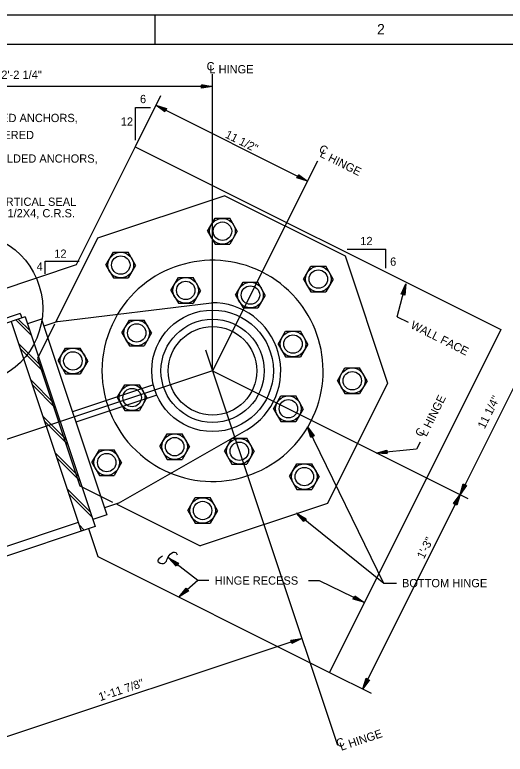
# Model space of a CAD drawing. Extents: x 0.1 to 13.5, y 0.1 to 9.5.
# Drawn here: x 7.414 to 10.186, y 5.277 to 9.458 of the extents above; entities that cross this region are included whole.
import ezdxf

# ---------------------------------------------------------------- set-up
doc = ezdxf.new("R2010")
doc.units = 0
for name, color, linetype in [('Level 1', 7, 'Continuous'), ('Level 13', 7, 'Continuous'), ('Level 25', 7, 'Continuous'), ('Level 3', 7, 'Continuous'), ('Level 44', 7, 'Continuous'), ('Level 50', 7, 'Continuous')]:
    doc.layers.add(name, color=color, linetype=linetype)

msp = doc.modelspace()

# ---------------------------------------------------------------- linework, layer by layer
at = {"layer": 'Level 1'}
for p, q in [((8.2083, 9.2917), (8.2083, 9.4583)), ((8.532, 7.445), (8.532, 9.1229)), ((8.0959, 8.7486), (8.0959, 8.9346)), ((8.0959, 8.9346), (8.1812, 8.9346)), ((8.2113, 8.9466), (9.0685, 8.518)), ((9.2936, 8.1324), (9.5107, 8.1324)), ((9.5107, 8.0265), (9.5107, 8.1324)), ((7.5853, 7.9944), (7.5853, 8.0646)), ((7.5853, 8.0646), (7.7779, 8.0646)), ((9.5758, 7.7512), (9.625, 7.9362)), ((9.5758, 7.7512), (9.6384, 7.7199)), ((10.3502, 7.5841), (9.9309, 6.7456)), ((8.4925, 7.5636), (9.2376, 5.3283)), ((8.532, 7.445), (9.9751, 6.7235)), ((9.7047, 7.0415), (9.6849, 7.0021)), ((9.9309, 6.7456), (9.3812, 5.6462)), ((9.1935, 5.74), (9.429, 5.6223))]:
    msp.add_line(p, q, dxfattribs=at)
for points in [[(0.125, 9.4583), (13.4583, 9.4583), (13.4583, 0.125), (0.125, 0.125)], [(0.625, 9.2917), (13.2917, 9.2917), (13.2917, 0.2917), (0.625, 0.2917)]]:
    msp.add_lwpolyline(points, close=True, dxfattribs=at)
msp.add_spline([(8.2493, 6.3964), (8.2228, 6.3676), (8.2541, 6.3555), (8.2926, 6.4085), (8.3239, 6.4181), (8.3311, 6.4037)], degree=3, dxfattribs=at)
at = {"layer": 'Level 13'}
for p, q in [((8.5043, 8.2349), (8.5463, 8.3076)), ((8.5463, 8.3076), (8.6299, 8.3076)), ((8.6719, 8.2349), (8.6299, 8.3076)), ((8.5043, 8.2349), (8.5463, 8.1622)), ((8.6719, 8.2349), (8.6299, 8.1622)), ((8.5463, 8.1622), (8.6299, 8.1622)), ((7.9295, 8.0433), (7.9715, 8.116)), ((7.9715, 8.116), (8.0551, 8.116)), ((8.0971, 8.0433), (8.0551, 8.116)), ((7.9295, 8.0433), (7.9715, 7.9705)), ((8.0971, 8.0433), (8.0551, 7.9705)), ((9.0463, 7.9639), (9.0883, 8.0366)), ((9.0883, 8.0366), (9.1719, 8.0366)), ((9.2139, 7.9639), (9.1719, 8.0366)), ((7.9715, 7.9705), (8.0551, 7.9705)), ((8.2967, 7.8998), (8.3387, 7.9725)), ((8.3387, 7.9725), (8.4223, 7.9725)), ((8.4643, 7.8998), (8.4223, 7.9725)), ((8.6625, 7.8738), (8.7045, 7.9465)), ((8.7045, 7.9465), (8.7881, 7.9465)), ((8.8301, 7.8738), (8.7881, 7.9465)), ((9.0463, 7.9639), (9.0883, 7.8912)), ((9.2139, 7.9639), (9.1719, 7.8912)), ((8.2967, 7.8998), (8.3387, 7.8271)), ((8.4643, 7.8998), (8.4223, 7.8271)), ((8.6625, 7.8738), (8.7045, 7.8011)), ((8.8301, 7.8738), (8.7881, 7.8011)), ((9.0883, 7.8912), (9.1719, 7.8912)), ((8.3387, 7.8271), (8.4223, 7.8271)), ((8.7045, 7.8011), (8.7881, 7.8011)), ((8.0196, 7.6595), (8.0616, 7.7322)), ((8.0616, 7.7322), (8.1452, 7.7322)), ((8.1872, 7.6595), (8.1452, 7.7322)), ((8.0196, 7.6595), (8.0616, 7.5868)), ((8.1872, 7.6595), (8.1452, 7.5868)), ((8.9028, 7.5967), (8.9448, 7.6695)), ((8.9448, 7.6695), (9.0284, 7.6695)), ((9.0704, 7.5967), (9.0284, 7.6695)), ((7.6585, 7.5013), (7.7005, 7.574)), ((7.7005, 7.574), (7.7841, 7.574)), ((7.8261, 7.5013), (7.7841, 7.574)), ((8.0616, 7.5868), (8.1452, 7.5868)), ((8.9028, 7.5967), (8.9448, 7.524)), ((9.0704, 7.5967), (9.0284, 7.524)), ((7.6585, 7.5013), (7.7005, 7.4286)), ((7.8261, 7.5013), (7.7841, 7.4286)), ((8.9448, 7.524), (9.0284, 7.524)), ((9.2379, 7.3891), (9.2799, 7.4618)), ((9.2799, 7.4618), (9.3635, 7.4618)), ((9.4055, 7.3891), (9.3635, 7.4618)), ((7.7005, 7.4286), (7.7841, 7.4286)), ((7.9936, 7.2937), (8.0356, 7.3664)), ((8.0356, 7.3664), (8.1192, 7.3664)), ((8.1612, 7.2937), (8.1192, 7.3664)), ((9.2379, 7.3891), (9.2799, 7.3164)), ((9.4055, 7.3891), (9.3635, 7.3164)), ((7.9936, 7.2937), (8.0356, 7.221)), ((8.1612, 7.2937), (8.1192, 7.221)), ((8.8768, 7.2309), (8.9188, 7.3036)), ((8.9188, 7.3036), (9.0024, 7.3036)), ((9.0444, 7.2309), (9.0024, 7.3036)), ((9.2799, 7.3164), (9.3635, 7.3164)), ((8.0356, 7.221), (8.1192, 7.221)), ((8.8768, 7.2309), (8.9188, 7.1582)), ((9.0444, 7.2309), (9.0024, 7.1582)), ((8.9188, 7.1582), (9.0024, 7.1582)), ((8.2339, 7.0166), (8.2759, 7.0894)), ((8.2759, 7.0894), (8.3595, 7.0894)), ((8.4015, 7.0166), (8.3595, 7.0894)), ((8.5997, 6.9906), (8.6417, 7.0634)), ((8.6417, 7.0634), (8.7253, 7.0634)), ((8.7673, 6.9906), (8.7253, 7.0634)), ((7.8501, 6.9265), (7.8921, 6.9992)), ((7.8921, 6.9992), (7.9757, 6.9992)), ((8.0177, 6.9265), (7.9757, 6.9992)), ((8.2339, 7.0166), (8.2759, 6.9439)), ((8.4015, 7.0166), (8.3595, 6.9439)), ((8.5997, 6.9906), (8.6417, 6.9179)), ((8.7673, 6.9906), (8.7253, 6.9179)), ((8.2759, 6.9439), (8.3595, 6.9439)), ((7.8501, 6.9265), (7.8921, 6.8538)), ((8.0177, 6.9265), (7.9757, 6.8538)), ((8.6417, 6.9179), (8.7253, 6.9179)), ((8.9669, 6.8471), (9.0089, 6.9199)), ((9.0089, 6.9199), (9.0925, 6.9199)), ((9.1345, 6.8471), (9.0925, 6.9199)), ((7.8921, 6.8538), (7.9757, 6.8538)), ((8.9669, 6.8471), (9.0089, 6.7744)), ((9.1345, 6.8471), (9.0925, 6.7744)), ((9.0089, 6.7744), (9.0925, 6.7744)), ((8.3921, 6.6555), (8.4341, 6.7283)), ((8.4341, 6.7283), (8.5177, 6.7283)), ((8.5597, 6.6555), (8.5177, 6.7283)), ((8.3921, 6.6555), (8.4341, 6.5828)), ((8.5597, 6.6555), (8.5177, 6.5828)), ((8.4341, 6.5828), (8.5177, 6.5828))]:
    msp.add_line(p, q, dxfattribs=at)
for centre in [(8.5881, 8.2347), (8.0133, 8.0431), (9.1301, 7.9637), (8.3805, 7.8996), (8.7463, 7.8736), (8.1034, 7.6593), (8.9866, 7.5965), (7.7423, 7.5011), (9.3217, 7.3889), (8.0774, 7.2935), (8.9606, 7.2307), (8.3177, 7.0164), (8.6835, 6.9904), (7.9339, 6.9263), (9.0507, 6.8469), (8.4759, 6.6553)]:
    msp.add_circle(centre, 0.0725, dxfattribs=at)
at = {"layer": 'Level 25'}
for p, q in [((8.532, 9.053), (6.3151, 9.053)), ((8.2379, 8.9997), (8.0941, 8.7121)), ((8.0941, 8.7121), (7.7601, 8.0442)), ((8.0941, 8.7121), (10.1624, 7.6779)), ((9.1252, 8.6314), (8.532, 7.445)), ((8.6023, 8.4347), (7.8819, 8.1946)), ((8.6023, 8.4347), (9.2816, 8.0951)), ((7.8819, 8.1946), (7.6461, 7.723)), ((9.2816, 8.0951), (9.5217, 7.3747)), ((7.7601, 8.0442), (7.0398, 7.8041)), ((7.6573, 7.7244), (8.5256, 7.8304)), ((7.4448, 7.7689), (5.3399, 7.0673)), ((7.4728, 7.7508), (5.3482, 7.0426)), ((7.4448, 7.7689), (7.4531, 7.7442)), ((7.4728, 7.7508), (7.8681, 6.5649)), ((7.5651, 7.7376), (7.486, 7.7113)), ((7.5651, 7.7376), (7.934, 6.6308)), ((7.3938, 7.7244), (7.7891, 6.5386)), ((7.6388, 7.7084), (7.5423, 7.5154)), ((7.6573, 7.7244), (7.5782, 7.6981)), ((10.1624, 7.6779), (9.1935, 5.74)), ((7.5423, 7.5154), (7.7824, 6.795)), ((8.532, 7.445), (5.337, 6.38)), ((8.1974, 7.3664), (7.7396, 7.2138)), ((9.5217, 7.3747), (9.1821, 6.6955)), ((8.2171, 7.3071), (7.7594, 7.1546)), ((7.9999, 6.6967), (8.7255, 7.1117)), ((7.7824, 6.7949), (7.9671, 6.7026)), ((7.9999, 6.6967), (7.9208, 6.6703)), ((7.9901, 6.6911), (8.4617, 6.4553)), ((9.1821, 6.6955), (8.4617, 6.4553)), ((7.934, 6.6308), (7.8549, 6.6044)), ((7.7726, 6.588), (5.727, 5.9061)), ((7.8681, 6.5649), (5.7435, 5.8567)), ((7.831, 6.5526), (7.8835, 6.395)), ((7.8835, 6.395), (9.1935, 5.74)), ((9.0362, 5.9324), (7.1487, 5.3032))]:
    msp.add_line(p, q, dxfattribs=at)
for centre, radius in [((8.5881, 8.2347), 0.0521), ((7.1424, 7.7968), 0.4297), ((8.0133, 8.0431), 0.0521), ((9.1301, 7.9637), 0.0521), ((8.3805, 7.8996), 0.0521), ((8.7463, 7.8736), 0.0521), ((8.532, 7.445), 0.3438), ((8.532, 7.445), 0.2917), ((8.1034, 7.6593), 0.0521), ((8.532, 7.445), 0.25), ((8.9866, 7.5965), 0.0521), ((7.7423, 7.5011), 0.0521), ((9.3217, 7.3889), 0.0521), ((8.0774, 7.2935), 0.0521), ((8.9606, 7.2307), 0.0521), ((8.3177, 7.0164), 0.0521), ((8.6835, 6.9904), 0.0521), ((7.9339, 6.9263), 0.0521), ((9.0507, 6.8469), 0.0521), ((8.4759, 6.6553), 0.0521)]:
    msp.add_circle(centre, radius, dxfattribs=at)
for radius, start, end in [(0.625, 243.8888, 149.1319), (0.3854, 300.1282, 90.9539), (0.625, 149.1319, 247.8392), (0.625, 152.8609, 153.0479)]:
    msp.add_arc((8.532, 7.445), radius, start, end, dxfattribs=at)
at = {"layer": 'Level 3'}
for p, q in [((9.0692, 7.1281), (9.0692, 7.1281)), ((9.0768, 7.1125), (9.0768, 7.1125)), ((9.6849, 7.0021), (9.4563, 6.98)), ((9.4563, 6.98), (9.4563, 6.98)), ((9.4736, 6.9817), (9.4736, 6.9817)), ((9.4999, 6.2424), (9.0066, 6.6395)), ((9.0066, 6.6395), (9.0066, 6.6395)), ((9.0201, 6.6287), (9.0201, 6.6287)), ((8.449, 6.2593), (8.283, 6.3868)), ((8.283, 6.3868), (8.283, 6.3868)), ((8.2967, 6.3763), (8.2967, 6.3763)), ((8.3431, 6.1678), (8.3431, 6.1678)), ((8.3563, 6.1791), (8.3563, 6.1791)), ((9.3718, 6.1441), (9.3718, 6.1441)), ((9.3874, 6.1365), (9.3874, 6.1365))]:
    msp.add_line(p, q, dxfattribs=at)
for points in [[(9.5721, 6.2424), (9.4999, 6.2424), (9.0692, 7.1281)], [(9.0871, 7.0676), (9.0692, 7.1281), (9.1057, 7.0766), (9.0898, 7.0689), (9.0768, 7.1125), (9.1016, 7.0775), (9.0914, 7.0726), (9.084, 7.0976), (9.0974, 7.0785), (9.0932, 7.0764), (9.0916, 7.082)], [(9.5194, 6.9757), (9.4563, 6.98), (9.5174, 6.9963), (9.5191, 6.9787), (9.4736, 6.9817), (9.515, 6.9927), (9.5161, 6.9814), (9.4902, 6.9833), (9.5127, 6.9891), (9.5131, 6.9845), (9.5074, 6.9849)], [(9.0487, 6.5924), (9.0066, 6.6395), (9.0616, 6.6085), (9.0506, 6.5947), (9.0201, 6.6287), (9.0575, 6.6076), (9.0504, 6.5988), (9.0331, 6.6182), (9.0533, 6.6067), (9.0504, 6.603), (9.0466, 6.6073)], [(8.3261, 6.3406), (8.283, 6.3868), (8.3387, 6.357), (8.3279, 6.343), (8.2967, 6.3763), (8.3346, 6.356), (8.3277, 6.347), (8.3099, 6.3661), (8.3304, 6.355), (8.3276, 6.3513), (8.3237, 6.3556)], [(8.5116, 6.2593), (8.449, 6.2593), (8.3431, 6.1678)], [(9.0746, 6.2593), (9.1348, 6.2593), (9.3874, 6.1365)], [(8.3971, 6.2007), (8.3431, 6.1678), (8.3836, 6.2164), (8.3951, 6.203), (8.3563, 6.1791), (8.3837, 6.2121), (8.3911, 6.2035), (8.3689, 6.19), (8.3839, 6.2078), (8.3869, 6.2043), (8.382, 6.2014)], [(9.3358, 6.173), (9.3874, 6.1365), (9.3268, 6.1545), (9.3345, 6.1703), (9.3718, 6.1441), (9.3307, 6.1563), (9.3356, 6.1665), (9.3568, 6.1514), (9.3345, 6.1581), (9.3366, 6.1623), (9.3412, 6.1589)]]:
    msp.add_lwpolyline(points, dxfattribs=at)
at = {"layer": 'Level 44'}
for p, q in [((7.499, 7.6724), (7.4337, 7.7377)), ((7.5084, 7.6441), (7.4195, 7.733)), ((7.5673, 7.4674), (7.4355, 7.5991)), ((7.5767, 7.4391), (7.445, 7.5709)), ((7.6357, 7.2623), (7.5039, 7.3941)), ((7.6451, 7.234), (7.5133, 7.3658)), ((7.704, 7.0573), (7.5723, 7.189)), ((7.7134, 7.029), (7.5817, 7.1607)), ((7.7724, 6.8522), (7.6406, 6.9839)), ((7.7818, 6.8239), (7.65, 6.9557)), ((7.8407, 6.6471), (7.709, 6.7789)), ((7.8502, 6.6188), (7.7184, 6.7506)), ((7.8067, 6.5445), (7.7773, 6.5738)), ((7.7926, 6.5397), (7.7868, 6.5455))]:
    msp.add_line(p, q, dxfattribs=at)
at = {"layer": 'Level 50'}
for p, q in [((8.5147, 9.053), (8.5147, 9.053)), ((8.532, 9.053), (8.532, 9.053)), ((8.2113, 8.9466), (8.2113, 8.9466)), ((8.2268, 8.9388), (8.2268, 8.9388)), ((9.053, 8.5258), (9.053, 8.5258)), ((9.0685, 8.518), (9.0685, 8.518)), ((9.6205, 7.9195), (9.6205, 7.9195)), ((9.625, 7.9362), (9.625, 7.9362)), ((9.9309, 6.7456), (9.9309, 6.7456)), ((9.9309, 6.7456), (9.9309, 6.7456)), ((9.9387, 6.7611), (9.9387, 6.7611)), ((9.9232, 6.7301), (9.9232, 6.7301)), ((9.0198, 5.9269), (9.0198, 5.9269)), ((9.0362, 5.9324), (9.0362, 5.9324)), ((9.3812, 5.6462), (9.3812, 5.6462)), ((9.3889, 5.6617), (9.3889, 5.6617))]:
    msp.add_line(p, q, dxfattribs=at)
for points in [[(8.4697, 9.0634), (8.532, 9.053), (8.4697, 9.0427), (8.4697, 9.0604), (8.5147, 9.053), (8.4723, 9.046), (8.4723, 9.0574), (8.498, 9.053), (8.475, 9.0494), (8.475, 9.054), (8.4807, 9.053)], [(8.2624, 8.9095), (8.2113, 8.9466), (8.2717, 8.9279), (8.2638, 8.9121), (8.2268, 8.9388), (8.2678, 8.9261), (8.2627, 8.916), (8.2417, 8.9314), (8.2639, 8.9244), (8.2618, 8.9202), (8.2572, 8.9236)], [(9.0174, 8.5551), (9.0685, 8.518), (9.0081, 8.5366), (9.016, 8.5524), (9.053, 8.5258), (9.012, 8.5384), (9.0171, 8.5486), (9.0381, 8.5332), (9.0159, 8.5402), (9.018, 8.5444), (9.0226, 8.541)], [(9.599, 7.8786), (9.625, 7.9362), (9.619, 7.8733), (9.6019, 7.8779), (9.6205, 7.9195), (9.6164, 7.8768), (9.6055, 7.8797), (9.6163, 7.9034), (9.6139, 7.8802), (9.6094, 7.8814), (9.6118, 7.8866)], [(9.968, 6.7967), (9.9309, 6.7456), (9.9496, 6.8059), (9.9654, 6.798), (9.9387, 6.7611), (9.9513, 6.8021), (9.9615, 6.797), (9.9461, 6.776), (9.9531, 6.7982), (9.9573, 6.7961), (9.9539, 6.7915)], [(9.8938, 6.6944), (9.9309, 6.7456), (9.9123, 6.6852), (9.8965, 6.6931), (9.9232, 6.7301), (9.9105, 6.6891), (9.9004, 6.6941), (9.9157, 6.7152), (9.9087, 6.6929), (9.9045, 6.695), (9.908, 6.6996)], [(8.9738, 5.9225), (9.0362, 5.9324), (8.9803, 5.9029), (8.9747, 5.9196), (9.0198, 5.9269), (8.9818, 5.9069), (8.9782, 5.9176), (9.0039, 5.9216), (8.9833, 5.9109), (8.9818, 5.9153), (8.9875, 5.9162)], [(9.4183, 5.6973), (9.3812, 5.6462), (9.3998, 5.7065), (9.4156, 5.6986), (9.3889, 5.6617), (9.4016, 5.7027), (9.4118, 5.6976), (9.3964, 5.6766), (9.4034, 5.6988), (9.4076, 5.6967), (9.4041, 5.6921)]]:
    msp.add_lwpolyline(points, dxfattribs=at)

# ---------------------------------------------------------------- texts
at = {"layer": 'Level 1'}
for s, height, p in [('2', 0.0584, (9.4623, 9.348)), ('C', 0.0467, (8.4983, 9.144)), ('L HINGE', 0.0467, (8.5139, 9.1271)), ('2\'-2 1/4"', 0.0467, (7.338, 9.096)), ('6', 0.0467, (8.1217, 8.9587)), ("1/2 0 X 6'' WELDED ANCHORS,", 0.046698, (6.8651, 8.8516)), ('12', 0.0467, (8.0131, 8.8311)), ("12'' O.C., STAGGERED", 0.046698, (6.8568, 8.7553)), ("1/2 0 X 6'' WELDED ANCHORS,", 0.046698, (6.9772, 8.6222)), ('VERTICAL SEAL', 0.046698, (7.2792, 8.378)), ('PL 1/2X4, C.R.S.', 0.046698, (7.2787, 8.313)), ('12', 0.0467, (9.3672, 8.1557)), ('12', 0.0467, (7.6372, 8.0842)), ('6', 0.0467, (9.5359, 8.0393)), ('4', 0.0467, (7.5377, 8.0116)), ('HINGE RECESS', 0.046698, (8.5441, 6.2359)), ('BOTTOM HINGE', 0.046698, (9.6028, 6.2215))]:
    msp.add_text(s, height=height, dxfattribs=at).set_placement(p)
for s, height, rotation, p in [('11 1/2"', 0.0467, 333.4353, (8.5991, 8.7661)), ('C', 0.0467, 333.435, (9.1292, 8.6852)), ('L HINGE', 0.0467, 333.435, (9.1345, 8.6573)), ('WALL FACE', 0.0467, 333.435, (9.6477, 7.6886)), ("11 1/4''", 0.0467, 63.4338, (10.0696, 7.1132)), ('1\'-3"', 0.0467, 63.4338, (9.7263, 6.3781)), ("1'-11 7/8''", 0.046698, 18.435, (7.897, 5.5772)), ('L HINGE', 0.0467, 18.4352, (9.2595, 5.2962)), ('C', 0.0467, 18.4352, (9.2402, 5.3146))]:
    msp.add_text(s, height=height, rotation=rotation, dxfattribs=at).set_placement(p)
at = {"layer": 'Level 3'}
for s, height, p in [('L HINGE', 0.04679, (9.7407, 7.07)), ('C', 0.0468, (9.7164, 7.0676))]:
    msp.add_text(s, height=height, rotation=63.4338, dxfattribs=at).set_placement(p)

doc.saveas('drawing.dxf')
